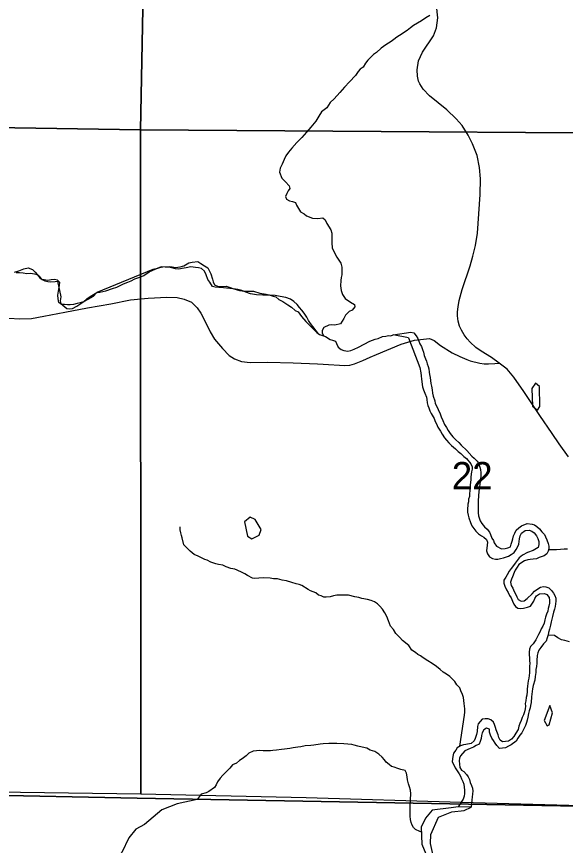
# Model space of a CAD drawing. Extents: x 0 to 34, y 0 to 22.
# Drawn here: x 28.944 to 29.781, y 17.785 to 19.051 of the extents above; entities that cross this region are included whole.
import ezdxf

# ---------------------------------------------------------------- set-up
doc = ezdxf.new("R2010")
doc.units = 0
for name, color, linetype in [('GM_X_Adjacent_County', 7, 'Continuous'), ('GM_X_County', 7, 'Continuous'), ('GM_X_County_Road', 7, 'Continuous'), ('GM_X_Minor_Lake', 7, 'Continuous'), ('GM_X_Minor_River', 7, 'Continuous'), ('GM_X_Section', 7, 'Continuous'), ('GM_X_Section_Text', 7, 'Continuous'), ('GM_X_State_Route', 7, 'Continuous'), ('GM_X_Township', 7, 'Continuous')]:
    doc.layers.add(name, color=color, linetype=linetype)

msp = doc.modelspace()

# ---------------------------------------------------------------- linework, layer by layer
at = {"layer": 'GM_X_Adjacent_County'}
for points in [[(30.8167, 17.8174), (30.1304, 17.8301), (29.8296, 17.8449), (29.1279, 17.8574), (28.6324, 17.8677)], [(28.6324, 17.8677), (29.1279, 17.8574), (29.8296, 17.8449), (30.1304, 17.8301), (30.8167, 17.8174)]]:
    msp.add_lwpolyline(points, dxfattribs=at)
at = {"layer": 'GM_X_County'}
for points in [[(28.6324, 17.8677), (29.1279, 17.8574), (29.8296, 17.8449), (30.1304, 17.8301), (30.8167, 17.8174)], [(30.8167, 17.8174), (30.1304, 17.8301), (29.8296, 17.8449), (29.1279, 17.8574), (28.6324, 17.8677)]]:
    msp.add_lwpolyline(points, dxfattribs=at)
at = {"layer": 'GM_X_County_Road'}
for points in [[(28.9324, 18.5903), (28.949, 18.5892), (28.9671, 18.5899), (28.9859, 18.5935), (29.0179, 18.5992), (29.0523, 18.6058), (29.0881, 18.6122), (29.1179, 18.6182), (29.145, 18.6209), (29.1733, 18.6224), (29.1891, 18.6216), (29.1997, 18.619), (29.211, 18.6148), (29.2196, 18.6058), (29.2253, 18.598), (29.2322, 18.5841), (29.2396, 18.5692), (29.2461, 18.558), (29.2581, 18.544), (29.2682, 18.5334), (29.2767, 18.5282), (29.2871, 18.5243), (29.3007, 18.5228), (29.3271, 18.5232), (29.3658, 18.522), (29.4033, 18.5207), (29.4118, 18.5202), (29.4448, 18.5182), (29.4523, 18.5186), (29.4597, 18.5204), (29.4721, 18.5256), (29.4836, 18.5305)], [(29.4836, 18.5305), (29.4931, 18.5346), (29.5309, 18.5504), (29.5511, 18.5569), (29.5738, 18.5592), (29.581, 18.5559), (29.591, 18.5487), (29.6087, 18.5375), (29.6205, 18.5315), (29.6311, 18.5272)], [(29.6311, 18.5272), (29.636, 18.5252), (29.6506, 18.5213), (29.6576, 18.5206), (29.6641, 18.5206), (29.6736, 18.5208), (29.6804, 18.5217)]]:
    msp.add_lwpolyline(points, dxfattribs=at)
at = {"layer": 'GM_X_Minor_Lake'}
for points in [[(29.7416, 18.4857), (29.7359, 18.491), (29.7302, 18.4827), (29.731, 18.4561)], [(29.731, 18.4561), (29.739, 18.4497), (29.7424, 18.4554), (29.7416, 18.4857)], [(29.317, 18.2678), (29.3083, 18.283), (29.3003, 18.2864), (29.292, 18.2792)], [(29.292, 18.2792), (29.2962, 18.2572), (29.3031, 18.2534), (29.314, 18.2591), (29.317, 18.2678)], [(29.7574, 17.9987), (29.7491, 17.9759), (29.7537, 17.9679), (29.7567, 17.9695)], [(29.7567, 17.9695), (29.7616, 17.9877), (29.7574, 17.9987)]]:
    msp.add_lwpolyline(points, dxfattribs=at)
at = {"layer": 'GM_X_Minor_River'}
for p, q in [((29.542, 18.5604), (29.5187, 18.5649)), ((29.6375, 17.8439), (29.618, 17.8444))]:
    msp.add_line(p, q, dxfattribs=at)
for points in [[(29.5747, 19.0524), (29.5682, 19.0489), (29.5618, 19.0444), (29.5497, 19.0368), (29.5452, 19.0337), (29.5402, 19.0292), (29.5285, 19.0219), (29.524, 19.0193), (29.5198, 19.0155), (29.5153, 19.0128), (29.5073, 19.0075), (29.5002, 19.0022), (29.4934, 18.9957), (29.4888, 18.9927), (29.4801, 18.9839), (29.4764, 18.9794), (29.4726, 18.9733), (29.4684, 18.9706), (29.4654, 18.9668), (29.4613, 18.9607), (29.4518, 18.9509), (29.4443, 18.9429), (29.4371, 18.9345), (29.4284, 18.925), (29.4227, 18.9197), (29.4174, 18.9113), (29.4095, 18.9053), (29.4054, 18.8984), (29.4008, 18.8912), (29.3929, 18.8817), (29.3865, 18.8741), (29.3793, 18.8658), (29.3718, 18.8582), (29.3642, 18.8498), (29.3589, 18.8437), (29.3548, 18.838), (29.3525, 18.8327), (29.3491, 18.8251), (29.3461, 18.8194), (29.345, 18.813), (29.3488, 18.8039), (29.3545, 18.7986), (29.3598, 18.7921), (29.361, 18.7884)], [(29.361, 18.7884), (29.3583, 18.7846), (29.3565, 18.7808), (29.3546, 18.7762), (29.3557, 18.7717), (29.3603, 18.7694), (29.3652, 18.7683), (29.3698, 18.7668), (29.3709, 18.7626), (29.3743, 18.7577), (29.3774, 18.7527), (29.3827, 18.7493), (29.3865, 18.7467), (29.3956, 18.7429), (29.4039, 18.7426), (29.4111, 18.7433), (29.4149, 18.7403), (29.4176, 18.7346), (29.4233, 18.7251), (29.4248, 18.7202), (29.4252, 18.7157), (29.4249, 18.7111), (29.4249, 18.7054), (29.4257, 18.6975), (29.4287, 18.691), (29.4325, 18.6834), (29.439, 18.674), (29.4405, 18.6679), (29.4402, 18.6565), (29.4391, 18.6524), (29.4387, 18.6478), (29.438, 18.6395), (29.4391, 18.6323), (29.4414, 18.6262), (29.4456, 18.6201), (29.4536, 18.6145), (29.4596, 18.6111), (29.46, 18.6073), (29.4559, 18.6023), (29.4513, 18.6004), (29.4457, 18.5947), (29.4434, 18.5898), (29.4408, 18.5856), (29.4385, 18.5818), (29.4294, 18.5795), (29.4245, 18.5799), (29.4203, 18.5795), (29.4128, 18.5761), (29.4101, 18.5715), (29.4101, 18.5673), (29.4128, 18.5629)], [(28.9411, 18.6604), (28.9476, 18.6623), (28.9551, 18.6653), (28.9616, 18.6672), (28.9684, 18.6646), (28.9726, 18.6604), (28.976, 18.6563), (28.979, 18.6525), (28.9832, 18.6495), (28.9874, 18.6472), (28.9919, 18.6461), (28.9961, 18.6457), (29.0029, 18.6461), (29.0067, 18.6465), (29.0117, 18.6226), (29.0106, 18.6165), (29.0117, 18.6124), (29.0209, 18.6052), (29.0247, 18.6044), (29.0292, 18.6048), (29.036, 18.6086), (29.0405, 18.6117), (29.0466, 18.6159), (29.0515, 18.62), (29.0564, 18.6235), (29.0666, 18.6292), (29.0712, 18.6299), (29.0803, 18.6322), (29.0905, 18.6353), (29.0969, 18.6376), (29.1071, 18.6425), (29.1136, 18.6452), (29.1189, 18.6471), (29.1246, 18.6502), (29.1321, 18.6528), (29.1382, 18.6555), (29.1465, 18.6608), (29.1563, 18.6654), (29.1628, 18.6677), (29.1673, 18.6688), (29.1776, 18.6689), (29.1817, 18.6685), (29.1866, 18.6677), (29.1938, 18.6685), (29.1991, 18.67), (29.2067, 18.6746), (29.212, 18.6758), (29.2207, 18.6769), (29.2253, 18.6735), (29.231, 18.6701), (29.2359, 18.6671), (29.2405, 18.658), (29.2428, 18.65), (29.2439, 18.6459), (29.2462, 18.6413), (29.2504, 18.6391), (29.2546, 18.6387), (29.2637, 18.6391), (29.2701, 18.6372), (29.2739, 18.6357), (29.2792, 18.6342), (29.2841, 18.6327), (29.2925, 18.6316), (29.3004, 18.6312), (29.3057, 18.6312), (29.3152, 18.6286), (29.3247, 18.6271), (29.3293, 18.626), (29.3357, 18.6237), (29.3395, 18.6226), (29.3444, 18.6188), (29.3505, 18.6158)], [(29.4049, 18.5661), (29.3923, 18.5821), (29.3896, 18.5866), (29.3869, 18.5919), (29.3828, 18.598), (29.3793, 18.6025), (29.3755, 18.6063), (29.3721, 18.6109), (29.3672, 18.6158), (29.3622, 18.6192), (29.3547, 18.6218), (29.3463, 18.6233), (29.3384, 18.6248), (29.33, 18.6252), (29.3198, 18.6252), (29.3103, 18.6259), (29.3008, 18.6274), (29.294, 18.63), (29.2876, 18.6323), (29.2815, 18.6342), (29.2743, 18.6349), (29.2644, 18.6361), (29.2599, 18.6364), (29.2527, 18.6368), (29.247, 18.6375), (29.2432, 18.6387), (29.239, 18.6451), (29.236, 18.6493), (29.2333, 18.6565), (29.2306, 18.6618), (29.2261, 18.6659), (29.2215, 18.6671), (29.217, 18.6678), (29.2098, 18.6685), (29.2029, 18.667), (29.1965, 18.6659), (29.1916, 18.6651), (29.1867, 18.6655), (29.1787, 18.6677), (29.1707, 18.6681), (29.1647, 18.6685), (29.1571, 18.6658), (29.1522, 18.6643), (29.0663, 18.6292), (29.061, 18.6235), (29.0527, 18.6189), (29.0462, 18.6151), (29.0409, 18.6136), (29.0368, 18.6124), (29.0307, 18.6113), (29.0258, 18.6105), (29.0216, 18.6105), (29.0174, 18.6109), (29.0125, 18.6112), (29.0087, 18.6139), (29.0076, 18.6196), (29.0072, 18.6256), (29.0079, 18.6317), (29.009, 18.637), (29.0098, 18.6408), (29.0101, 18.6446), (29.0063, 18.6484), (29.0022, 18.6491), (28.9969, 18.6487), (28.9919, 18.6476), (28.9832, 18.6491), (28.9794, 18.6533), (28.9756, 18.6563), (28.9714, 18.6574), (28.9654, 18.6582), (28.9597, 18.6581), (28.9544, 18.6589), (28.9487, 18.6593), (28.9434, 18.6596)], [(29.3505, 18.6158), (29.3581, 18.6105), (29.3634, 18.6071), (29.3691, 18.6021), (29.3737, 18.5999), (29.379, 18.5927), (29.3855, 18.5851), (29.3927, 18.5779), (29.398, 18.5722), (29.4022, 18.5681), (29.4064, 18.5651), (29.4155, 18.562), (29.4223, 18.5575), (29.4261, 18.5568), (29.4306, 18.5552), (29.4322, 18.5515), (29.4345, 18.5461), (29.4394, 18.5424), (29.4432, 18.5409), (29.4492, 18.5401), (29.4538, 18.5409), (29.4591, 18.5428), (29.4659, 18.5458), (29.4746, 18.5504), (29.4829, 18.555), (29.4913, 18.558), (29.4958, 18.5592), (29.5022, 18.5622), (29.5072, 18.563), (29.5113, 18.5638), (29.5151, 18.5634), (29.5187, 18.5649)], [(29.5187, 18.5649), (29.5454, 18.5688), (29.55, 18.5676), (29.5538, 18.5631), (29.5561, 18.5593), (29.5576, 18.5551), (29.5595, 18.551), (29.5618, 18.5468), (29.5633, 18.5423), (29.5648, 18.5381), (29.566, 18.5332), (29.5679, 18.5282), (29.5694, 18.5244), (29.5706, 18.5203), (29.5721, 18.5165), (29.5729, 18.5127), (29.5736, 18.5078), (29.574, 18.504), (29.5748, 18.4994), (29.5756, 18.4952), (29.576, 18.4903), (29.5771, 18.4865), (29.5779, 18.4808), (29.5787, 18.4759), (29.5798, 18.471), (29.5821, 18.4642), (29.5829, 18.46), (29.5848, 18.4562), (29.5871, 18.4509), (29.5901, 18.4441), (29.592, 18.4395), (29.5943, 18.4342), (29.597, 18.4278), (29.6, 18.4232), (29.6027, 18.4187), (29.6057, 18.4141), (29.6095, 18.4092), (29.6141, 18.4043), (29.619, 18.4005), (29.6225, 18.3963), (29.6308, 18.388), (29.6384, 18.3797), (29.6422, 18.3763), (29.6468, 18.3717), (29.6491, 18.3679), (29.651, 18.363), (29.6517, 18.3592), (29.6525, 18.3543), (29.6522, 18.349), (29.6518, 18.3448), (29.6503, 18.3327), (29.6492, 18.3255), (29.6488, 18.319), (29.6485, 18.3114), (29.6485, 18.3069), (29.6481, 18.3016), (29.6481, 18.297), (29.6485, 18.2932), (29.6489, 18.2883), (29.6512, 18.2807), (29.6539, 18.2769), (29.6581, 18.2716), (29.6619, 18.2682), (29.6653, 18.2637), (29.6672, 18.2599), (29.6691, 18.2546), (29.6714, 18.2508), (29.6725, 18.247), (29.676, 18.2424), (29.6839, 18.2379), (29.6892, 18.2387), (29.6934, 18.2398), (29.6976, 18.241), (29.6987, 18.2451), (29.7002, 18.2497), (29.7009, 18.2535), (29.7024, 18.2577), (29.7043, 18.2618), (29.7062, 18.2668), (29.7104, 18.2702), (29.7145, 18.2733), (29.7229, 18.2767), (29.7304, 18.2759), (29.7342, 18.2748), (29.738, 18.2722), (29.7418, 18.2688), (29.7456, 18.2642), (29.7494, 18.26), (29.751, 18.2563), (29.7532, 18.2517), (29.7548, 18.2464), (29.7559, 18.2422), (29.7559, 18.2381), (29.7552, 18.2343), (29.7529, 18.2305), (29.7488, 18.2274), (29.7412, 18.2248), (29.737, 18.2228), (29.7321, 18.2225), (29.7276, 18.2217), (29.7238, 18.2213)], [(29.542, 18.5604), (29.5592, 18.5149), (29.5608, 18.5066), (29.5611, 18.5024), (29.5619, 18.4971), (29.5623, 18.4933), (29.5627, 18.4891), (29.5635, 18.4854), (29.565, 18.4808), (29.5669, 18.4759), (29.5692, 18.4698), (29.57, 18.466), (29.5707, 18.4611), (29.5715, 18.4569), (29.573, 18.4531), (29.5746, 18.449), (29.5765, 18.4448), (29.581, 18.4372), (29.5829, 18.4327), (29.5849, 18.4289), (29.5868, 18.4236), (29.5906, 18.4175), (29.5932, 18.4133), (29.5967, 18.4077), (29.5997, 18.4039), (29.6035, 18.3997), (29.6077, 18.3956), (29.6138, 18.3906), (29.6179, 18.3868), (29.6217, 18.3838), (29.6263, 18.3793), (29.6305, 18.3759), (29.6373, 18.3679), (29.6389, 18.3634), (29.6389, 18.3596), (29.6381, 18.3558), (29.6378, 18.352), (29.637, 18.3474), (29.637, 18.3433), (29.6363, 18.3357), (29.6359, 18.3307), (29.6355, 18.327), (29.6352, 18.322), (29.6348, 18.3182), (29.6337, 18.3137), (29.6333, 18.3099), (29.6326, 18.3061), (29.6318, 18.2977), (29.6322, 18.2939), (29.633, 18.2894), (29.6342, 18.2856), (29.6365, 18.2784), (29.6387, 18.2731), (29.6418, 18.2689), (29.6448, 18.2651), (29.6486, 18.261), (29.6532, 18.2579), (29.657, 18.2557), (29.6612, 18.2523), (29.6623, 18.2481), (29.6619, 18.2435), (29.6612, 18.2352), (29.6624, 18.2307), (29.6654, 18.2261), (29.67, 18.2231), (29.6745, 18.2223), (29.6783, 18.2223), (29.6825, 18.2231), (29.687, 18.2243), (29.6946, 18.2269), (29.6987, 18.2292), (29.7033, 18.2326), (29.7063, 18.2372), (29.7086, 18.2414), (29.7101, 18.2452), (29.7108, 18.2493), (29.7112, 18.2535), (29.7123, 18.2577), (29.7146, 18.2619), (29.7202, 18.2661), (29.7263, 18.2664), (29.7301, 18.2649), (29.7339, 18.2623), (29.7373, 18.2581), (29.7392, 18.254), (29.7407, 18.2494), (29.7408, 18.2449), (29.74, 18.2403), (29.7321, 18.2357), (29.7234, 18.2323), (29.7158, 18.2285), (29.7109, 18.2243), (29.7075, 18.2205), (29.7048, 18.2163), (29.7022, 18.2125), (29.6988, 18.208), (29.6958, 18.2038), (29.6924, 18.1985), (29.6905, 18.1947), (29.6875, 18.1901), (29.6875, 18.1856)], [(29.6205, 17.9369), (29.6275, 17.984), (29.6278, 17.9885), (29.6278, 17.9938), (29.627, 18.0022), (29.6266, 18.0067), (29.6259, 18.0113), (29.6243, 18.0155), (29.622, 18.0211), (29.6201, 18.0261), (29.6156, 18.0306), (29.6129, 18.0355), (29.6091, 18.0393), (29.6049, 18.0431), (29.6, 18.0465), (29.5951, 18.0499), (29.5905, 18.0537), (29.5848, 18.0582), (29.578, 18.0628), (29.5715, 18.0673), (29.5643, 18.0719), (29.5601, 18.0745), (29.5563, 18.0768), (29.5525, 18.0798), (29.5472, 18.0836), (29.5426, 18.0904), (29.5328, 18.098), (29.529, 18.1025), (29.5225, 18.1086), (29.5191, 18.115), (29.5145, 18.1199), (29.5115, 18.1283), (29.5088, 18.1347), (29.5061, 18.1404), (29.5023, 18.1461), (29.4985, 18.1506), (29.4947, 18.154), (29.4902, 18.1571), (29.4852, 18.159), (29.4792, 18.1608), (29.4708, 18.1623), (29.4663, 18.1638), (29.4602, 18.165), (29.4503, 18.1672), (29.4447, 18.1676), (29.4386, 18.1676), (29.4329, 18.1676), (29.4276, 18.1664), (29.4223, 18.1649), (29.4166, 18.1645), (29.4128, 18.1645), (29.409, 18.1664), (29.4045, 18.1675), (29.4007, 18.1709), (29.3927, 18.1739), (29.3889, 18.1762), (29.3794, 18.1822), (29.3753, 18.1834), (29.3707, 18.1845), (29.3639, 18.1868), (29.3559, 18.189), (29.3491, 18.1901), (29.3419, 18.1924), (29.3362, 18.1924), (29.3309, 18.1935), (29.3214, 18.1939), (29.3138, 18.1931), (29.3078, 18.1927), (29.304, 18.1935), (29.2964, 18.1972), (29.2922, 18.1999), (29.2884, 18.2022), (29.2808, 18.2055), (29.2771, 18.2071), (29.271, 18.2082), (29.2638, 18.2104), (29.2588, 18.2131), (29.2524, 18.2142), (29.2482, 18.2153), (29.2403, 18.2176), (29.2349, 18.2206), (29.2312, 18.2218), (29.2274, 18.224), (29.2209, 18.2267), (29.2148, 18.2293), (29.2091, 18.2346), (29.2031, 18.2399), (29.1993, 18.2444), (29.1966, 18.2547), (29.1958, 18.2585), (29.1947, 18.2623), (29.1935, 18.2672), (29.1935, 18.2717)], [(29.7557, 18.237), (29.7677, 18.2373), (29.7741, 18.2377), (29.7794, 18.2381), (29.7847, 18.2381)], [(29.7238, 18.2213), (29.7189, 18.2198), (29.7105, 18.2141), (29.7079, 18.2103), (29.7049, 18.2057), (29.703, 18.2019), (29.7007, 18.1955), (29.6992, 18.1917), (29.6977, 18.1871), (29.6985, 18.1822), (29.7012, 18.178), (29.7034, 18.1731), (29.705, 18.1693), (29.7073, 18.1647), (29.7095, 18.1609), (29.7141, 18.1583), (29.7186, 18.1587), (29.7228, 18.1621), (29.7304, 18.1693), (29.7341, 18.1735), (29.7391, 18.1769), (29.7432, 18.1796), (29.7478, 18.1808), (29.7516, 18.18), (29.7561, 18.1785), (29.7603, 18.1743), (29.7633, 18.1705), (29.7652, 18.1668), (29.7668, 18.1626), (29.7668, 18.158), (29.7664, 18.1539), (29.7657, 18.1501), (29.7645, 18.1459), (29.7634, 18.1413), (29.7619, 18.1349), (29.7597, 18.1265), (29.7585, 18.1216), (29.757, 18.1155), (29.7555, 18.1106), (29.7548, 18.1068), (29.7533, 18.1022), (29.7518, 18.0973), (29.748, 18.0931), (29.7439, 18.0874), (29.7408, 18.0832), (29.7393, 18.0794), (29.7382, 18.0753), (29.7375, 18.0677), (29.7375, 18.0635), (29.7371, 18.0582), (29.7364, 18.054), (29.736, 18.0495), (29.7353, 18.0434), (29.7345, 18.0377), (29.7323, 18.0293), (29.7312, 18.0244), (29.7308, 18.0202), (29.7301, 18.0161), (29.7297, 18.0119), (29.729, 18.0035), (29.7282, 17.999), (29.7275, 17.9952), (29.7263, 17.9906), (29.7252, 17.9868), (29.7241, 17.9811), (29.723, 17.9766), (29.7218, 17.9728), (29.7203, 17.9686), (29.7147, 17.9572), (29.712, 17.9534), (29.709, 17.9489), (29.7064, 17.9447), (29.6988, 17.939), (29.6943, 17.9367), (29.6901, 17.9344), (29.6856, 17.9336), (29.681, 17.9333), (29.6765, 17.9378), (29.6742, 17.9416), (29.6715, 17.9454), (29.6692, 17.9492), (29.667, 17.9537), (29.6658, 17.9583), (29.6654, 17.9628), (29.6609, 17.9643), (29.6567, 17.9617), (29.6544, 17.9571), (29.6533, 17.9533), (29.6526, 17.9484), (29.6514, 17.9438), (29.6496, 17.94), (29.6454, 17.9377), (29.6409, 17.9354), (29.6363, 17.9335), (29.628, 17.9297), (29.6212, 17.9221), (29.6197, 17.9183), (29.6193, 17.9145), (29.6197, 17.9092), (29.6205, 17.9043), (29.6228, 17.9001)], [(29.6875, 18.1856), (29.689, 18.181), (29.6913, 18.1757), (29.694, 18.1712), (29.6963, 18.167), (29.6986, 18.1632), (29.7008, 18.1583), (29.7027, 18.1537), (29.705, 18.1499), (29.7088, 18.1477), (29.713, 18.1469), (29.7175, 18.1473), (29.7236, 18.1492), (29.7281, 18.1507), (29.7331, 18.158), (29.7346, 18.1621), (29.7372, 18.1663), (29.7417, 18.1694), (29.7493, 18.1701), (29.7531, 18.1682), (29.7565, 18.1637), (29.7573, 18.1592), (29.7573, 18.155), (29.7562, 18.1508), (29.7551, 18.147), (29.7543, 18.1428), (29.7524, 18.1383), (29.7509, 18.1337), (29.7502, 18.1299), (29.7487, 18.1246), (29.7468, 18.1201), (29.7445, 18.1159), (29.743, 18.1117), (29.7404, 18.1071), (29.7385, 18.1033), (29.7363, 18.0992), (29.7321, 18.0931), (29.7283, 18.0889), (29.7268, 18.0847), (29.7261, 18.0802), (29.7261, 18.076), (29.7265, 18.0722), (29.7265, 18.0677), (29.7269, 18.0631), (29.7265, 18.0589), (29.7265, 18.0548), (29.7265, 18.0487), (29.7262, 18.0445), (29.7254, 18.0407), (29.7247, 18.0365), (29.7239, 18.0327), (29.7236, 18.0282), (29.7232, 18.024), (29.7228, 18.0202), (29.7225, 18.0149), (29.7217, 18.0111), (29.721, 18.0058), (29.7202, 18.002), (29.7203, 17.9978), (29.7199, 17.9937), (29.7188, 17.9891), (29.7176, 17.9849), (29.7154, 17.9804), (29.7139, 17.9758), (29.7116, 17.9716), (29.7105, 17.9675), (29.7094, 17.9625), (29.7056, 17.9568), (29.7026, 17.9515), (29.6992, 17.9473), (29.6946, 17.9443), (29.6855, 17.9435), (29.6817, 17.9458), (29.6798, 17.9499), (29.6787, 17.9541), (29.6756, 17.9617), (29.6745, 17.9655), (29.6733, 17.9697), (29.6714, 17.9734), (29.6676, 17.9769), (29.6635, 17.9784), (29.6589, 17.9784), (29.6544, 17.978), (29.6483, 17.9707), (29.6472, 17.9666), (29.6465, 17.959), (29.6457, 17.9544), (29.6435, 17.9487), (29.642, 17.9449), (29.6378, 17.9407), (29.6295, 17.9392), (29.6257, 17.9388), (29.6211, 17.9373), (29.6162, 17.9343), (29.614, 17.9305), (29.6106, 17.9259), (29.6094, 17.9213), (29.6091, 17.9175), (29.6087, 17.913), (29.611, 17.9084), (29.6133, 17.9035)], [(29.7874, 18.0959), (29.7806, 18.0981), (29.7753, 18.0992), (29.7696, 18.1023), (29.7647, 18.1057), (29.7547, 18.1065)], [(29.5447, 17.8464), (29.5456, 17.8639), (29.5448, 17.8696), (29.5433, 17.8745), (29.5421, 17.8795), (29.5406, 17.8855), (29.5398, 17.8901), (29.5387, 17.8958), (29.5368, 17.8996), (29.5303, 17.9014), (29.5258, 17.9026), (29.5201, 17.9048), (29.5163, 17.906), (29.5125, 17.909), (29.5079, 17.9124), (29.5056, 17.9162), (29.5018, 17.92), (29.4965, 17.9245), (29.4904, 17.9287), (29.4836, 17.9309), (29.4783, 17.934), (29.4711, 17.9351), (29.4646, 17.937), (29.4593, 17.9385), (29.4555, 17.9392), (29.4495, 17.94), (29.4434, 17.9403), (29.4328, 17.9411), (29.4207, 17.941), (29.412, 17.9403), (29.4074, 17.9399), (29.3976, 17.9383), (29.393, 17.9379), (29.3843, 17.9372), (29.3775, 17.936), (29.3733, 17.9353), (29.3658, 17.9341), (29.3608, 17.9333), (29.3529, 17.9322), (29.3483, 17.9318), (29.3404, 17.9306), (29.3351, 17.9302), (29.3313, 17.9299), (29.3267, 17.9298), (29.3203, 17.9298), (29.3146, 17.9302), (29.3101, 17.9298), (29.3048, 17.929), (29.2983, 17.926), (29.2942, 17.9222), (29.2885, 17.9176), (29.284, 17.915), (29.2798, 17.9111), (29.2737, 17.9081), (29.2692, 17.9032), (29.2586, 17.8925), (29.2549, 17.888), (29.2507, 17.8826), (29.2484, 17.8777), (29.2458, 17.8739), (29.2375, 17.8674), (29.2333, 17.8655), (29.2258, 17.8636), (29.2198, 17.8553)], [(29.6133, 17.9035), (29.616, 17.8993), (29.6194, 17.8948), (29.6213, 17.891), (29.6228, 17.8872), (29.6247, 17.8827), (29.6262, 17.8789), (29.627, 17.874), (29.6274, 17.8694), (29.6274, 17.8648), (29.6267, 17.8603), (29.6252, 17.8557), (29.618, 17.8444)], [(29.6228, 17.9001), (29.6266, 17.8979), (29.6307, 17.8937), (29.633, 17.8899), (29.6349, 17.8861), (29.6361, 17.8816), (29.638, 17.877), (29.6395, 17.8725), (29.6399, 17.8679), (29.6395, 17.8641), (29.6392, 17.8592), (29.6384, 17.855), (29.6375, 17.8439)], [(29.2198, 17.8553), (29.1892, 17.8486), (29.1658, 17.8394), (29.1394, 17.8173), (29.1258, 17.8101), (29.1156, 17.7968), (29.1047, 17.7747), (29.0915, 17.7625), (29.0655, 17.7461), (29.0568, 17.7362), (29.0459, 17.7297), (29.0334, 17.727), (29.0111, 17.7053), (28.9981, 17.659), (28.9801, 17.6157)], [(29.618, 17.8444), (29.607, 17.8428), (29.578, 17.839), (29.5679, 17.8268), (29.5615, 17.8131), (29.5623, 17.7873), (29.5788, 17.7479)], [(29.5806, 17.7654), (29.5756, 17.7881), (29.5763, 17.8022), (29.5875, 17.8284), (29.6079, 17.8364), (29.627, 17.8385), (29.6375, 17.8439)]]:
    msp.add_lwpolyline(points, dxfattribs=at)
msp.add_spline([(29.5617, 17.8056), (29.5528, 17.8097), (29.5447, 17.8464)], degree=3, dxfattribs=at)
at = {"layer": 'GM_X_Section'}
for points in [[(28.6801, 19.9157), (29.153, 19.9086), (29.1334, 18.8778), (28.6533, 18.8853), (28.6686, 19.4646)], [(29.153, 19.9086), (30.191, 19.8901), (30.1607, 18.8706), (29.1334, 18.8778)], [(28.6533, 18.8853), (29.1334, 18.8778), (29.1338, 17.8638), (28.8761, 17.867), (28.6324, 17.87), (28.6432, 18.3787), (28.6528, 18.8587)], [(29.1334, 18.8778), (30.1607, 18.8706), (30.1377, 17.8362), (29.8958, 17.8434), (29.6223, 17.851), (29.3858, 17.8581), (29.1338, 17.8638)]]:
    msp.add_lwpolyline(points, close=True, dxfattribs=at)
at = {"layer": 'GM_X_State_Route'}
msp.add_lwpolyline([(29.7859, 18.3785), (29.772, 18.3984), (29.7612, 18.4144), (29.7422, 18.4418), (29.7179, 18.4781), (29.7025, 18.5003), (29.6925, 18.5123), (29.6804, 18.5217), (29.6684, 18.5303), (29.653, 18.5399), (29.6448, 18.5457), (29.636, 18.5535), (29.6313, 18.5589), (29.6269, 18.565), (29.623, 18.572), (29.62, 18.5778), (29.6179, 18.5858), (29.6169, 18.5936), (29.6169, 18.5999), (29.6177, 18.6077), (29.6195, 18.6174), (29.6237, 18.634), (29.636, 18.6703), (29.6401, 18.6847), (29.6442, 18.7012), (29.647, 18.7201), (29.6511, 18.779), (29.6518, 18.8027), (29.6504, 18.8204), (29.6466, 18.8388), (29.6396, 18.8565), (29.6332, 18.8697), (29.6241, 18.8843), (29.6145, 18.8948), (29.6004, 18.9082), (29.574, 18.9298), (29.5645, 18.9396), (29.5594, 18.948), (29.5573, 18.952), (29.5558, 18.9599), (29.5551, 18.9695), (29.557, 18.9829), (29.5635, 18.9961), (29.58, 19.0212), (29.5848, 19.0336), (29.5867, 19.0485), (29.5846, 19.0674)], dxfattribs=at)
at = {"layer": 'GM_X_Township'}
for points in [[(30.8167, 17.8174), (30.1304, 17.8301), (29.8296, 17.8449), (29.1279, 17.8574), (28.6324, 17.8677), (28.1264, 17.8728), (27.8903, 17.8826), (27.7531, 17.8783), (27.1422, 17.8906), (26.9072, 17.9017), (26.4988, 17.9198), (26.3979, 17.9244), (26.2521, 17.9299), (26.228, 17.2045)], [(28.6324, 17.8677), (29.1279, 17.8574), (29.8296, 17.8449), (30.1304, 17.8301), (30.8167, 17.8174)]]:
    msp.add_lwpolyline(points, dxfattribs=at)

# ---------------------------------------------------------------- texts
at = {"layer": 'GM_X_Section_Text'}
msp.add_text('22', height=0.04186, rotation=0, dxfattribs=at).set_placement((29.608, 18.3288))

doc.saveas('drawing.dxf')
